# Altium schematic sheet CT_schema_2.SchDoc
size 406 x 311 mm
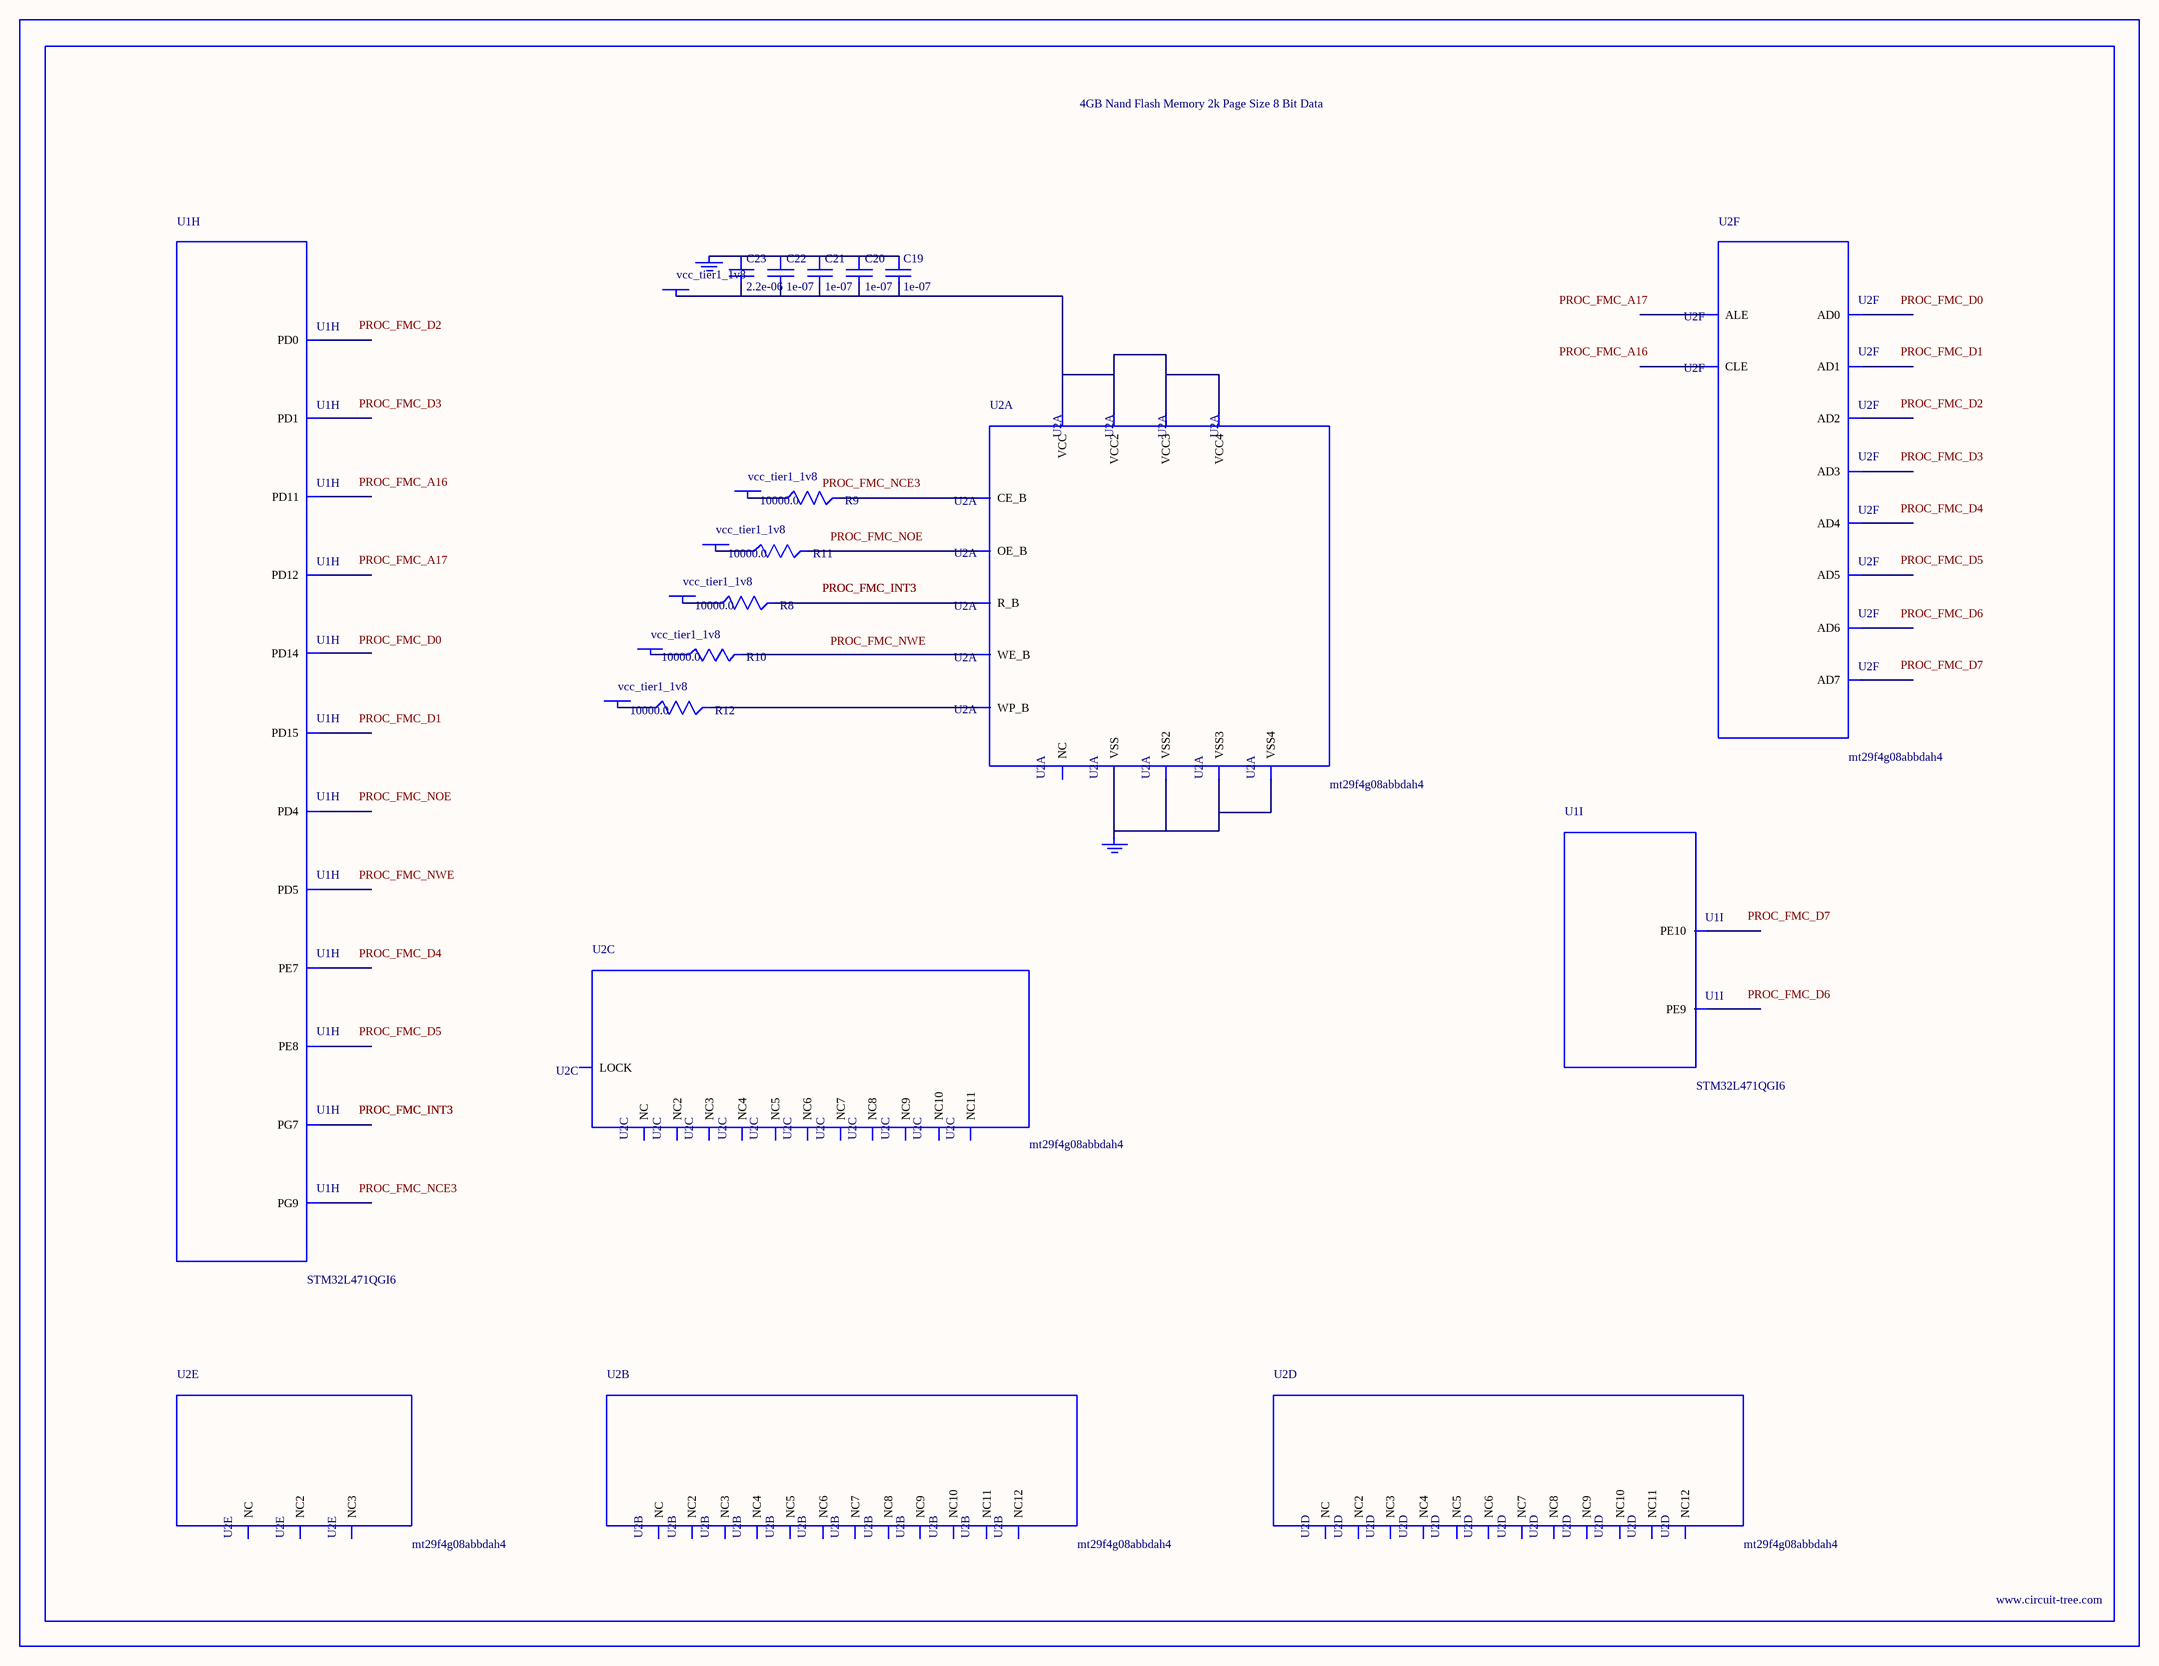
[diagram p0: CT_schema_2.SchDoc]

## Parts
BORDER1  (no value)
C19  1e-07  [C0402]
C20  1e-07  [C0402]
C21  1e-07  [C0402]
C22  1e-07  [C0402]
C23  2.2e-06  [C0603]
GND_INSTANCE_1_0  (no value)
GND_INSTANCE_1_1  (no value)
POWER_INSTANCE_1_0  vcc_tier1_1v8
POWER_INSTANCE_1_1  vcc_tier1_1v8
POWER_INSTANCE_1_2  vcc_tier1_1v8
POWER_INSTANCE_1_3  vcc_tier1_1v8
POWER_INSTANCE_1_4  vcc_tier1_1v8
POWER_INSTANCE_1_5  vcc_tier1_1v8
R8  10000.0  [R0603]
R9  10000.0  [R0603]
R10  10000.0  [R0603]
R11  10000.0  [R0603]
R12  10000.0  [R0603]
U1  STM32L471QGI6  [UFBGA132]  (parts H,I of 12)
U2  mt29f4g08abbdah4  [VFBGA-63]  (parts A,B,C,D,E,F of 6)

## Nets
NetC19_1: C19.1 C20.1 C21.1 C22.1 C23.1 GND_INSTANCE_1_0.0(GND)
NetC19_2: C19.2 C20.2 C21.2 C22.2 C23.2 POWER_INSTANCE_1_0.0(PWR) U2.D3(VCC) U2.G4(VCC2) U2.H8(VCC3) U2.J6(VCC4)
NetGND_INSTANCE_1_1_0: GND_INSTANCE_1_1.0(GND) U2.C5(VSS) U2.F7(VSS2) U2.K3(VSS3) U2.K8(VSS4)
NetPOWER_INSTANCE_1_1_0: POWER_INSTANCE_1_1.0(PWR) R8.1
NetPOWER_INSTANCE_1_2_0: POWER_INSTANCE_1_2.0(PWR) R9.1
NetPOWER_INSTANCE_1_3_0: POWER_INSTANCE_1_3.0(PWR) R10.1
NetPOWER_INSTANCE_1_4_0: POWER_INSTANCE_1_4.0(PWR) R11.1
NetPOWER_INSTANCE_1_5_0: POWER_INSTANCE_1_5.0(PWR) R12.1
NetR8_2: R8.2 U2.C8(R_B)
NetR9_2: R9.2 U2.C6(CE_B)
NetR10_2: R10.2 U2.C7(WE_B)
NetR11_2: R11.2 U2.D4(OE_B)
NetR12_2: R12.2 U2.C3(WP_B)

Not connected (* = marked no-connect by the designer): U1 A6(PD5) B7(PD4) B9(PD1) C9(PD0) D9(PG9) H4(PG7) H10(PD15) H11(PD14) J10(PD12) J11(PD11) L7(PE8) L8(PE10) M7(PE7) M8(PE9); U2 A1(NC) A2(NC3) A9(NC4) A10(NC2) B1(NC5) B9(NC7) B10(NC6) C4(ALE) D5(CLE) D6(NC8) D7(NC9) D8(NC10) E3(NC11) E4(NC12) E5(NC) E6(NC2) E7(NC3) E8(NC4) F3(NC5) F4(NC6) F5(NC7) F6(NC8) F8(NC9) G3(NC) G5(LOCK) G6(NC10) G7(NC11) G8(NC) H3(NC2) H4(AD0) H5(NC3) H6(NC4) H7(NC5) J3(NC6) J4(AD1) J5(NC7) J7(AD5) J8(AD7) K4(AD2) K5(AD3) K6(AD4) K7(AD6) L1(NC8) L2(NC10) L9(NC11) L10(NC9) M1(NC12) M2(NC2) M9(NC3) M10(NC)

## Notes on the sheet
- Labels drawn without touching a wire or pin: PROC_FMC_A16, PROC_FMC_A17, PROC_FMC_D0, PROC_FMC_D1, PROC_FMC_D2, PROC_FMC_D3, PROC_FMC_D4, PROC_FMC_D5, PROC_FMC_D6, PROC_FMC_D7, PROC_FMC_NCE3, PROC_FMC_NOE, PROC_FMC_NWE

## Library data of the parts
BORDER1 = BORDER_PAGE1
C19-C22 = C0402C104K3RACTU
C23 = C0603C225K8RACTU
GND_INSTANCE_1_0 GND_INSTANCE_1_1 = GND
POWER_INSTANCE_1_0-POWER_INSTANCE_1_5 = PWR
R8-R12 = RC0603JR-0710KL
